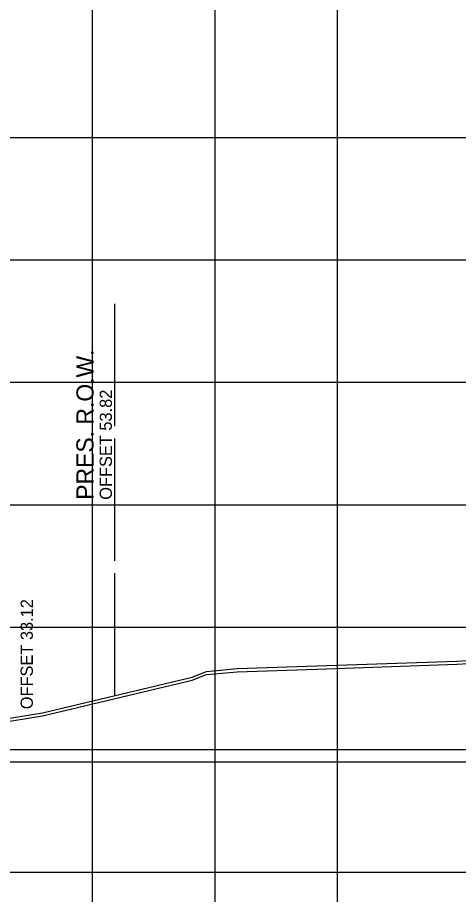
# Model space of a CAD drawing. Extents: x 1131015 to 1136271, y 133453 to 174329.
# Drawn here: x 1132374.3 to 1132410.3, y 158156.8 to 158228.4 of the extents above; entities that cross this region are included whole.
import ezdxf

# ---------------------------------------------------------------- set-up
doc = ezdxf.new("R2010")
doc.units = 0
for name, color, linetype in [('DESIGN - SHEET - Light Grid', 7, 'Continuous'), ('DESIGN - SHEET - Linework', 7, 'Continuous'), ('DESIGN - TYPICAL - Slope Tie Text', 7, 'Continuous'), ('SURVEY - GROUND - Bottom of Topsoil Layer', 7, 'Continuous'), ('SURVEY - GROUND - Top of Ground', 7, 'Continuous'), ('SURVEY - PROPERTY - ROW Lines', 7, 'Continuous'), ('SURVEY - PROPERTY - ROW Lines Text', 7, 'Continuous')]:
    doc.layers.add(name, color=color, linetype=linetype)

msp = doc.modelspace()

# ---------------------------------------------------------------- linework, layer by layer
at = {"layer": 'DESIGN - SHEET - Light Grid'}
msp.add_line((1132340.456, 158167.655), (1132640.456, 158167.655), dxfattribs=at)
at = {"layer": 'DESIGN - SHEET - Linework'}
for p, q in [((1132380.456, 158118.655), (1132380.456, 158328.655)), ((1132390.456, 158118.655), (1132390.456, 158328.655)), ((1132400.456, 158118.655), (1132400.456, 158328.655)), ((1132190.456, 158218.655), (1132490.456, 158218.655)), ((1132190.456, 158208.655), (1132490.456, 158208.655)), ((1132190.456, 158198.655), (1132490.456, 158198.655)), ((1132190.456, 158188.655), (1132490.456, 158188.655)), ((1132190.456, 158178.655), (1132490.456, 158178.655)), ((1132190.456, 158168.655), (1132490.456, 158168.655)), ((1132190.456, 158158.655), (1132490.456, 158158.655))]:
    msp.add_line(p, q, dxfattribs=at)
at = {"layer": 'SURVEY - GROUND - Bottom of Topsoil Layer'}
for p, q in [((1132398.755, 158175.238), (1132410.196, 158175.638)), ((1132410.196, 158175.638), (1132412.908, 158175.786)), ((1132389.762, 158174.785), (1132392.257, 158175.018)), ((1132392.257, 158175.018), (1132398.755, 158175.238)), ((1132376.375, 158171.401), (1132388.581, 158174.316)), ((1132388.581, 158174.316), (1132389.762, 158174.785)), ((1132370.069, 158170.393), (1132376.375, 158171.401))]:
    msp.add_line(p, q, dxfattribs=at)
at = {"layer": 'SURVEY - GROUND - Top of Ground'}
for p, q in [((1132398.755, 158175.488), (1132410.196, 158175.888)), ((1132410.196, 158175.888), (1132412.908, 158176.036)), ((1132388.581, 158174.566), (1132389.762, 158175.035)), ((1132389.762, 158175.035), (1132392.257, 158175.268)), ((1132392.257, 158175.268), (1132398.755, 158175.488)), ((1132376.375, 158171.651), (1132388.581, 158174.566)), ((1132370.069, 158170.643), (1132376.375, 158171.651))]:
    msp.add_line(p, q, dxfattribs=at)
at = {"layer": 'SURVEY - PROPERTY - ROW Lines'}
for p, q in [((1132382.279, 158195.061), (1132382.279, 158205.061)), ((1132382.279, 158184.061), (1132382.279, 158194.061)), ((1132382.279, 158173.061), (1132382.279, 158183.061))]:
    msp.add_line(p, q, dxfattribs=at)

# ---------------------------------------------------------------- texts
at = {"layer": 'DESIGN - TYPICAL - Slope Tie Text'}
msp.add_text('OFFSET 33.12', height=1, rotation=90, dxfattribs=at).set_placement((1132375.574, 158171.953))
at = {"layer": 'SURVEY - PROPERTY - ROW Lines Text'}
for s, height, p in [('PRES. R.O.W.', 1.4, (1132380.529, 158189.061)), ('OFFSET 53.82', 1, (1132382.029, 158189.061))]:
    msp.add_text(s, height=height, rotation=90, dxfattribs=at).set_placement(p)

doc.saveas('drawing.dxf')
